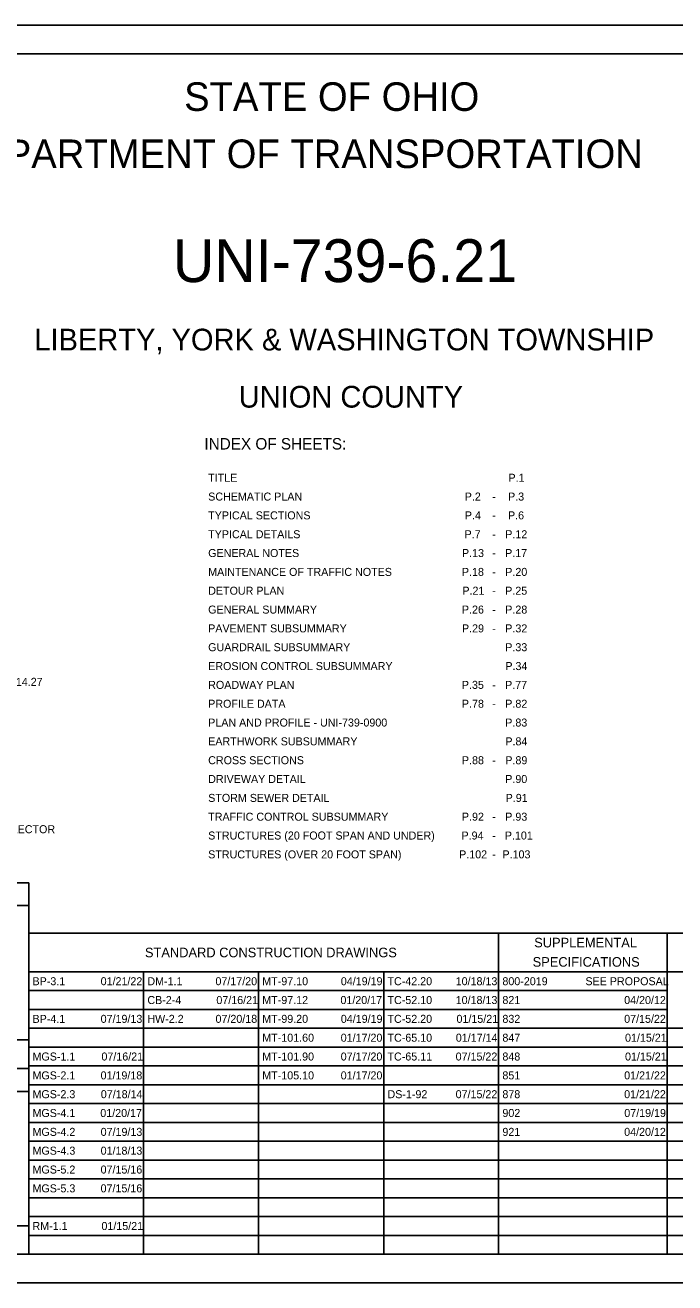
# Model space of a CAD drawing. Extents: x 0 to 34, y 0 to 22.
# Drawn here: x 11.19 to 22.55, y 0 to 22 of the extents above; entities that cross this region are included whole.
import ezdxf

# ---------------------------------------------------------------- set-up
doc = ezdxf.new("R2010")
doc.units = 0
for name, color, linetype in [('SH_Border', 7, 'Continuous'), ('SH_Cut_Line', 7, 'Continuous'), ('SH_Data', 7, 'Continuous'), ('SH_Text', 7, 'Continuous')]:
    doc.layers.add(name, color=color, linetype=linetype)

msp = doc.modelspace()

# ---------------------------------------------------------------- linework, layer by layer
at = {"layer": 'SH_Border'}
msp.add_lwpolyline([(1.5, 21.5), (33.5, 21.5), (33.5, 0.5), (1.5, 0.5)], close=True, dxfattribs=at)
at = {"layer": 'SH_Cut_Line'}
msp.add_lwpolyline([(0, 0), (34, 0), (34, 22), (0, 22)], close=True, dxfattribs=at)
at = {"layer": 'SH_Data'}
for p, q in [((8.45, 7), (11.25, 7)), ((11.25, 7), (11.25, 3.75)), ((8.45, 6.6), (11.25, 6.6)), ((8.45, 3.75), (11.25, 3.75)), ((8.45, 3.75), (11.25, 3.75)), ((8.45, 3.75), (11.25, 3.75)), ((11.25, 0.5), (11.25, 3.75)), ((11.25, 3.75), (11.25, 0.5)), ((11.25, 3.75), (11.25, 0.5)), ((8.45, 3.35), (11.25, 3.35)), ((8.45, 0.5), (11.25, 0.5)), ((8.45, 0.5), (11.25, 0.5))]:
    msp.add_line(p, q, dxfattribs=at)
for points in [[(8.45, 3.75), (8.45, 4.25), (11.25, 4.25), (11.25, 3.75)], [(8.45, 0.5), (8.45, 1), (11.25, 1), (11.25, 0.5)]]:
    msp.add_lwpolyline(points, close=True, dxfattribs=at)
at = {"layer": 'SH_Text'}
for p, q in [((11.25, 6.116), (24.641, 6.116)), ((11.25, 6.116), (11.25, 0.5)), ((19.469, 6.116), (19.469, 0.5)), ((22.417, 6.116), (22.417, 0.5)), ((11.25, 5.441), (24.641, 5.441)), ((13.259, 5.441), (13.259, 0.5)), ((15.269, 5.441), (15.269, 0.5)), ((17.459, 5.441), (17.459, 0.5)), ((11.25, 5.112), (22.417, 5.112)), ((11.25, 4.782), (22.417, 4.782)), ((11.25, 4.453), (24.641, 4.453)), ((11.25, 4.124), (24.641, 4.124)), ((11.25, 3.794), (24.641, 3.794)), ((11.25, 3.465), (24.641, 3.465)), ((11.25, 3.135), (24.641, 3.135)), ((11.25, 2.806), (24.641, 2.806)), ((11.25, 2.476), (24.641, 2.476)), ((11.25, 2.147), (24.641, 2.147)), ((11.25, 1.818), (24.641, 1.818)), ((11.25, 1.488), (24.641, 1.488)), ((11.25, 1.159), (24.641, 1.159)), ((11.25, 0.829), (24.641, 0.829)), ((11.25, 0.5), (24.641, 0.5))]:
    msp.add_line(p, q, dxfattribs=at)

# ---------------------------------------------------------------- texts
for s, height, p in [('STATE OF OHIO', 0.5, (13.968, 20.5)), ('DEPARTMENT OF TRANSPORTATION', 0.5, (9.92, 19.5)), ('UNI-739-6.21', 0.75, (13.772, 17.505)), ('LIBERTY, YORK & WASHINGTON TOWNSHIP', 0.38, (11.348, 16.31)), ('UNION COUNTY', 0.38, (14.923, 15.31)), ('INDEX OF SHEETS:', 0.2, (14.323, 14.577)), ('TITLE', 0.14, (14.389, 14.013)), ('P.1', 0.14, (19.641, 14.013)), ('SCHEMATIC PLAN', 0.14, (14.389, 13.684)), ('P.2', 0.14, (18.876, 13.684)), ('-', 0.14, (19.358, 13.684)), ('P.3', 0.14, (19.634, 13.684)), ('TYPICAL SECTIONS', 0.14, (14.389, 13.355)), ('P.4', 0.14, (18.878, 13.355)), ('P.6', 0.14, (19.633, 13.355)), ('-', 0.14, (19.358, 13.355)), ('TYPICAL DETAILS', 0.14, (14.389, 13.025)), ('P.7', 0.14, (18.873, 13.025)), ('-', 0.14, (19.358, 13.025)), ('P.12', 0.14, (19.585, 13.025)), ('GENERAL NOTES', 0.14, (14.389, 12.696)), ('P.13', 0.14, (18.828, 12.696)), ('P.17', 0.14, (19.582, 12.696)), ('-', 0.14, (19.358, 12.696)), ('MAINTENANCE OF TRAFFIC NOTES', 0.14, (14.389, 12.366)), ('P.18', 0.14, (18.827, 12.366)), ('-', 0.14, (19.358, 12.366)), ('P.20', 0.14, (19.585, 12.366)), ('DETOUR PLAN', 0.14, (14.389, 12.037)), ('P.21', 0.14, (18.835, 12.037)), ('P.25', 0.14, (19.584, 12.037)), ('-', 0.14, (19.358, 12.037)), ('GENERAL SUMMARY', 0.14, (14.389, 11.707)), ('P.26', 0.14, (18.827, 11.707)), ('-', 0.14, (19.358, 11.707)), ('P.28', 0.14, (19.585, 11.707)), ('PAVEMENT SUBSUMMARY', 0.14, (14.389, 11.378)), ('P.29', 0.14, (18.828, 11.378)), ('-', 0.14, (19.358, 11.378)), ('P.32', 0.14, (19.585, 11.378)), ('GUARDRAIL SUBSUMMARY', 0.14, (14.389, 11.049)), ('P.33', 0.14, (19.585, 11.049)), ('EROSION CONTROL SUBSUMMARY', 0.14, (14.389, 10.719)), ('P.34', 0.14, (19.587, 10.719)), ('SLM 11.51-14.27', 0.14, (10.057, 10.443)), ('ROADWAY PLAN', 0.14, (14.389, 10.39)), ('P.35', 0.14, (18.826, 10.39)), ('-', 0.14, (19.358, 10.39)), ('P.77', 0.14, (19.582, 10.39)), ('PROFILE DATA', 0.14, (14.389, 10.06)), ('P.78', 0.14, (18.827, 10.06)), ('-', 0.14, (19.358, 10.06)), ('P.82', 0.14, (19.585, 10.06)), ('PLAN AND PROFILE - UNI-739-0900', 0.14, (14.389, 9.731)), ('P.83', 0.14, (19.585, 9.731)), ('EARTHWORK SUBSUMMARY', 0.14, (14.389, 9.402)), ('P.84', 0.14, (19.587, 9.402)), ('CROSS SECTIONS', 0.14, (14.389, 9.072)), ('P.88', 0.14, (18.827, 9.072)), ('-', 0.14, (19.358, 9.072)), ('P.89', 0.14, (19.586, 9.072)), ('DRIVEWAY DETAIL', 0.14, (14.389, 8.743)), ('P.90', 0.14, (19.585, 8.743)), ('STORM SEWER DETAIL', 0.14, (14.389, 8.413)), ('P.91', 0.14, (19.592, 8.413)), ('TRAFFIC CONTROL SUBSUMMARY', 0.14, (14.389, 8.084)), ('P.92', 0.14, (18.827, 8.084)), ('-', 0.14, (19.358, 8.084)), ('P.93', 0.14, (19.585, 8.084)), ('MAJOR COLLECTOR ', 0.14, (9.86, 7.865)), ('STRUCTURES (20 FOOT SPAN AND UNDER)', 0.14, (14.389, 7.755)), ('P.94', 0.14, (18.819, 7.755)), ('-', 0.14, (19.358, 7.755)), ('P.101', 0.14, (19.577, 7.755)), ('STRUCTURES (OVER 20 FOOT SPAN)', 0.14, (14.389, 7.425)), ('P.102', 0.14, (18.778, 7.425)), ('-', 0.14, (19.358, 7.425)), ('P.103', 0.14, (19.536, 7.425)), ('SUPPLEMENTAL', 0.168, (20.091, 5.868)), ('STANDARD CONSTRUCTION DRAWINGS', 0.168, (13.283, 5.695)), ('SPECIFICATIONS', 0.168, (20.064, 5.53)), ('BP-3.1', 0.14, (11.316, 5.206)), ('01/21/22', 0.14, (12.508, 5.206)), ('DM-1.1', 0.14, (13.325, 5.206)), ('07/17/20', 0.14, (14.516, 5.206)), ('MT-97.10', 0.14, (15.335, 5.206)), ('04/19/19', 0.14, (16.709, 5.206)), ('TC-42.20', 0.14, (17.525, 5.206)), ('10/18/13', 0.14, (18.718, 5.206)), ('800-2019', 0.14, (19.535, 5.206)), ('SEE PROPOSAL', 0.14, (20.987, 5.206)), ('CB-2-4', 0.14, (13.325, 4.877)), ('07/16/21', 0.14, (14.532, 4.877)), ('MT-97.12', 0.14, (15.335, 4.877)), ('01/20/17', 0.14, (16.702, 4.877)), ('TC-52.10', 0.14, (17.525, 4.877)), ('10/18/13', 0.14, (18.718, 4.877)), ('821', 0.14, (19.535, 4.877)), ('04/20/12', 0.14, (21.665, 4.877)), ('BP-4.1', 0.14, (11.316, 4.548)), ('07/19/13', 0.14, (12.508, 4.548)), ('HW-2.2', 0.14, (13.325, 4.548)), ('07/20/18', 0.14, (14.517, 4.548)), ('MT-99.20', 0.14, (15.335, 4.548)), ('04/19/19', 0.14, (16.709, 4.548)), ('TC-52.20', 0.14, (17.525, 4.548)), ('01/15/21', 0.14, (18.732, 4.548)), ('832', 0.14, (19.535, 4.548)), ('07/15/22', 0.14, (21.665, 4.548)), ('MT-101.60', 0.14, (15.335, 4.218)), ('01/17/20', 0.14, (16.707, 4.218)), ('TC-65.10', 0.14, (17.525, 4.218)), ('01/17/14', 0.14, (18.72, 4.218)), ('847', 0.14, (19.535, 4.218)), ('01/15/21', 0.14, (21.68, 4.218)), ('MGS-1.1', 0.14, (11.316, 3.889)), ('07/16/21', 0.14, (12.522, 3.889)), ('MT-101.90', 0.14, (15.335, 3.889)), ('07/17/20', 0.14, (16.707, 3.889)), ('TC-65.11', 0.14, (17.525, 3.889)), ('07/15/22', 0.14, (18.717, 3.889)), ('848', 0.14, (19.535, 3.889)), ('01/15/21', 0.14, (21.68, 3.889)), ('MGS-2.1', 0.14, (11.316, 3.559)), ('01/19/18', 0.14, (12.507, 3.559)), ('MT-105.10', 0.14, (15.335, 3.559)), ('01/17/20', 0.14, (16.707, 3.559)), ('851', 0.14, (19.535, 3.559)), ('01/21/22', 0.14, (21.665, 3.559)), ('MGS-2.3', 0.14, (11.316, 3.23)), ('07/18/14', 0.14, (12.511, 3.23)), ('DS-1-92', 0.14, (17.525, 3.23)), ('07/15/22', 0.14, (18.717, 3.23)), ('878', 0.14, (19.535, 3.23)), ('01/21/22', 0.14, (21.665, 3.23)), ('MGS-4.1', 0.14, (11.316, 2.901)), ('01/20/17', 0.14, (12.502, 2.901)), ('902', 0.14, (19.535, 2.901)), ('07/19/19', 0.14, (21.667, 2.901)), ('MGS-4.2', 0.14, (11.316, 2.571)), ('07/19/13', 0.14, (12.508, 2.571)), ('921', 0.14, (19.535, 2.571)), ('04/20/12', 0.14, (21.665, 2.571)), ('MGS-4.3', 0.14, (11.316, 2.242)), ('01/18/13', 0.14, (12.508, 2.242)), ('MGS-5.2', 0.14, (11.316, 1.912)), ('07/15/16', 0.14, (12.507, 1.912)), ('MGS-5.3', 0.14, (11.316, 1.583)), ('07/15/16', 0.14, (12.507, 1.583)), ('RM-1.1', 0.14, (11.316, 0.924)), ('01/15/21', 0.14, (12.522, 0.924))]:
    msp.add_text(s, height=height, dxfattribs=at).set_placement(p)

doc.saveas('drawing.dxf')
